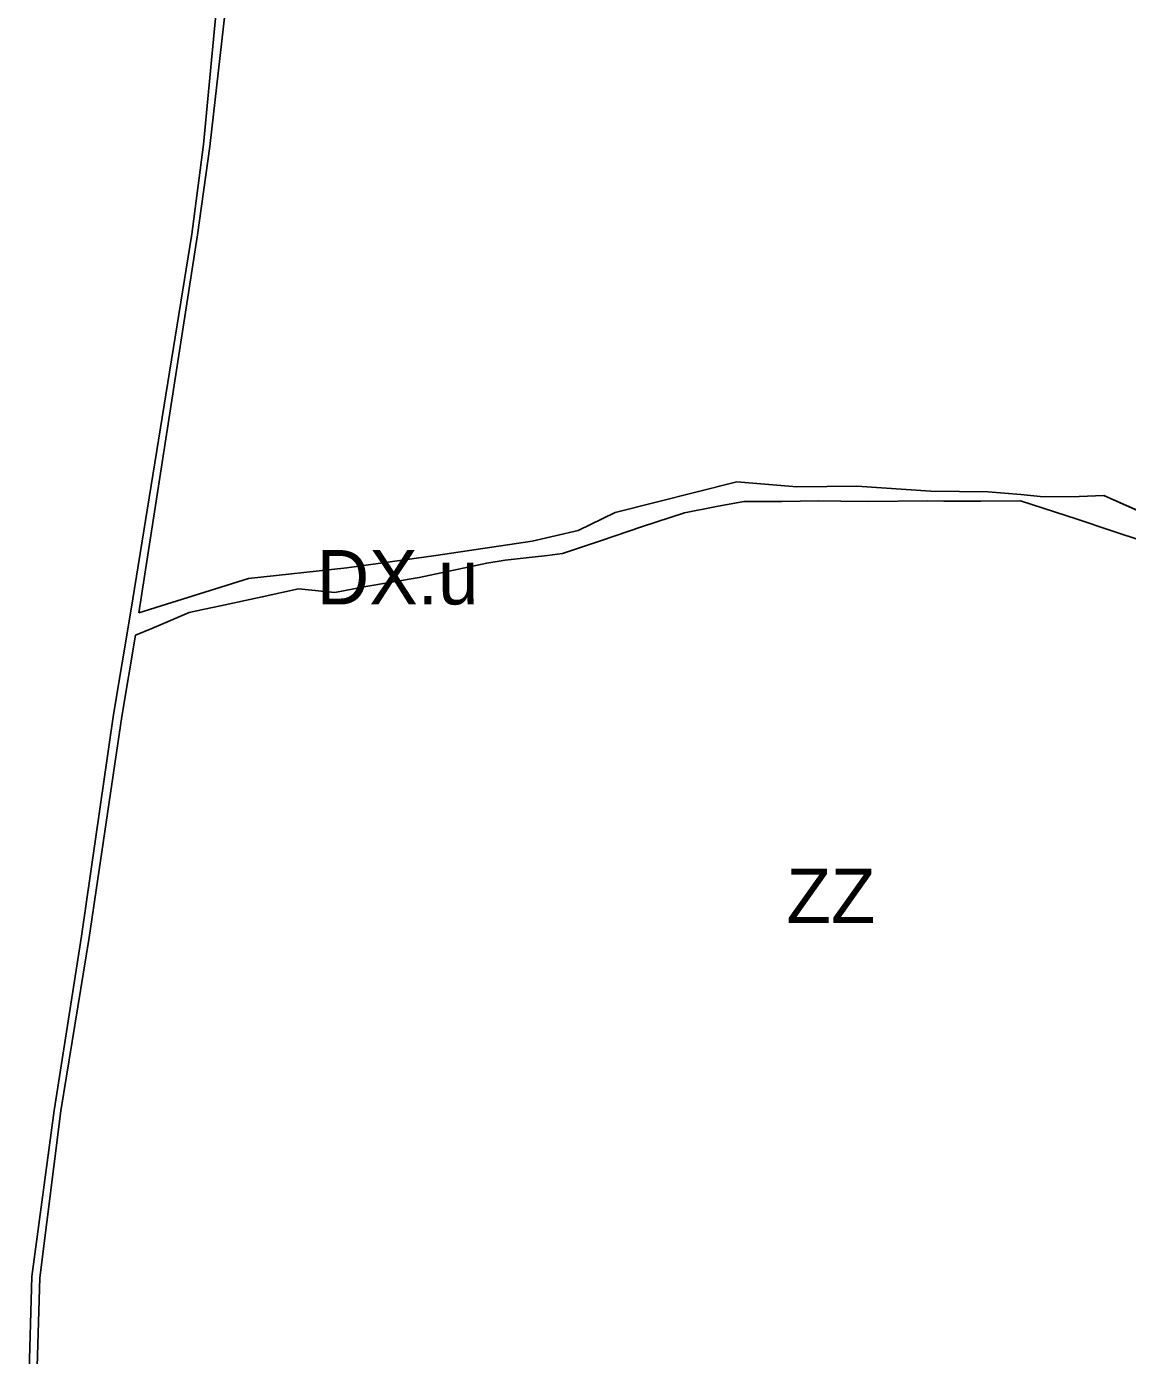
# Model space of a CAD drawing. Extents: x -555509 to -553005, y -1186756 to -1182560.
# Drawn here: x -555024.3 to -554741.3, y -1184380.7 to -1184039.1 of the extents above; entities that cross this region are included whole.
import ezdxf

# ---------------------------------------------------------------- set-up
doc = ezdxf.new("R2010")
doc.units = 0
for name, color, linetype in [('Level 26', 7, 'Continuous'), ('Level 59', 7, 'Continuous'), ('OBRYS_PLOCH', 7, 'Continuous'), ('stav_AP', 7, 'Continuous'), ('stav_ZZ', 7, 'Continuous')]:
    doc.layers.add(name, color=color, linetype=linetype)

msp = doc.modelspace()

# ---------------------------------------------------------------- linework, layer by layer
at = {"layer": 'Level 26'}
for p, q in [((-554977.25, -1184069.89), (-554972.59, -1184028.87)), ((-554981.81, -1184092.43), (-554997.53, -1184189.35)), ((-554841.71, -1184156.17), (-554872.97, -1184163.98)), ((-554777.04, -1184158.7), (-554791.86, -1184158.49)), ((-554753.68, -1184159.87), (-554762.83, -1184159.96)), ((-554747.36, -1184159.66), (-554753.68, -1184159.87)), ((-554872.97, -1184163.98), (-554882.51, -1184168.67)), ((-554882.51, -1184168.67), (-554894.36, -1184171.35)), ((-554967.28, -1184180.99), (-554995.48, -1184189.77)), ((-554997.53, -1184189.35), (-555002.02, -1184215.93)), ((-555002.02, -1184215.93), (-555010.19, -1184272.95)), ((-555010.19, -1184272.95), (-555017.27, -1184317.79)), ((-555017.27, -1184317.79), (-555022.95, -1184360.44))]:
    msp.add_line(p, q, dxfattribs=at)
for points in [[(-554971.89, -1183991.64), (-554974.97, -1184028.67), (-554978.81, -1184069.43), (-554981.81, -1184092.43)], [(-554995.48, -1184189.77), (-554980.39, -1184092.67), (-554977.25, -1184069.89)], [(-554791.86, -1184158.49), (-554810.85, -1184157.24), (-554826.25, -1184157.38), (-554841.71, -1184156.17)], [(-554996.33, -1184195.56), (-554992.16, -1184193.84), (-554982.55, -1184189.76), (-554978.55, -1184188.87), (-554974.47, -1184188.03), (-554963.73, -1184185.72), (-554954.41, -1184183.68), (-554945.1, -1184184.59), (-554937.1, -1184183.07), (-554923.4, -1184180.72), (-554906.02, -1184177.04), (-554901.25, -1184176.31), (-554894.31, -1184175.49), (-554890.43, -1184175.04), (-554886.56, -1184174.59), (-554876.77, -1184171.31), (-554865.93, -1184167.64), (-554855.16, -1184164.07), (-554846.93, -1184162.47), (-554839.91, -1184161.21)], [(-554839.91, -1184161.21), (-554835.01, -1184161.18), (-554830.1, -1184161.15), (-554820.74, -1184160.99), (-554814.94, -1184161.08), (-554807.82, -1184161.17), (-554792.65, -1184161.03), (-554788.5, -1184161.08), (-554779, -1184161.13), (-554768.81, -1184161.01), (-554754.23, -1184165.76)], [(-554762.83, -1184159.96), (-554768.67, -1184159.38), (-554777.04, -1184158.7)], [(-554718.94, -1184169.35), (-554731.96, -1184166.49), (-554747.36, -1184159.66)], [(-554754.23, -1184165.76), (-554745.55, -1184168.61), (-554737, -1184171.44), (-554731.66, -1184173.2), (-554726.32, -1184174.96), (-554718.61, -1184177.43), (-554714.69, -1184178.74), (-554710.61, -1184179.75)], [(-554894.36, -1184171.35), (-554919.07, -1184175.03), (-554942.01, -1184178.26), (-554967.28, -1184180.99)], [(-555019.26, -1184465.9), (-555022.34, -1184409.18), (-555020.93, -1184360.76), (-555015.55, -1184317.88), (-555008.27, -1184273.24), (-554999.82, -1184216.47), (-554996.33, -1184195.56)], [(-555022.95, -1184360.44), (-555024.33, -1184409.14), (-555021.51, -1184466.21)]]:
    msp.add_lwpolyline(points, dxfattribs=at)
at = {"layer": 'OBRYS_PLOCH'}
for p, q in [((-554977.25, -1184069.89), (-554972.59, -1184028.87)), ((-554972.59, -1184028.87), (-554977.25, -1184069.89)), ((-554981.81, -1184092.43), (-554997.53, -1184189.35)), ((-554841.71, -1184156.17), (-554872.97, -1184163.98)), ((-554872.97, -1184163.98), (-554841.71, -1184156.17)), ((-554841.71, -1184156.17), (-554826.25, -1184157.38)), ((-554826.25, -1184157.38), (-554810.85, -1184157.24)), ((-554810.85, -1184157.24), (-554791.86, -1184158.49)), ((-554839.91, -1184161.21), (-554846.93, -1184162.47)), ((-554835.01, -1184161.18), (-554839.91, -1184161.21)), ((-554830.1, -1184161.15), (-554835.01, -1184161.18)), ((-554820.74, -1184160.99), (-554830.1, -1184161.15)), ((-554814.94, -1184161.08), (-554820.74, -1184160.99)), ((-554807.82, -1184161.17), (-554814.94, -1184161.08)), ((-554792.65, -1184161.03), (-554807.82, -1184161.17)), ((-554788.5, -1184161.08), (-554792.65, -1184161.03)), ((-554777.04, -1184158.7), (-554791.86, -1184158.49)), ((-554791.86, -1184158.49), (-554777.04, -1184158.7)), ((-554779, -1184161.13), (-554788.5, -1184161.08)), ((-554777.04, -1184158.7), (-554768.67, -1184159.38)), ((-554753.68, -1184159.87), (-554762.83, -1184159.96)), ((-554747.36, -1184159.66), (-554753.68, -1184159.87)), ((-554753.68, -1184159.87), (-554747.36, -1184159.66)), ((-554747.36, -1184159.66), (-554731.96, -1184166.49)), ((-554872.97, -1184163.98), (-554882.51, -1184168.67)), ((-554882.51, -1184168.67), (-554872.97, -1184163.98)), ((-554865.93, -1184167.64), (-554876.77, -1184171.31)), ((-554882.51, -1184168.67), (-554894.36, -1184171.35)), ((-554894.36, -1184171.35), (-554882.51, -1184168.67)), ((-554876.77, -1184171.31), (-554886.56, -1184174.59)), ((-554886.56, -1184174.59), (-554890.43, -1184175.04)), ((-554967.28, -1184180.99), (-554942.01, -1184178.26)), ((-554901.25, -1184176.31), (-554906.02, -1184177.04)), ((-554967.28, -1184180.99), (-554995.48, -1184189.77)), ((-554995.48, -1184189.77), (-554967.28, -1184180.99)), ((-554954.41, -1184183.68), (-554963.73, -1184185.72)), ((-554945.1, -1184184.59), (-554954.41, -1184183.68)), ((-554937.1, -1184183.07), (-554945.1, -1184184.59)), ((-554974.47, -1184188.03), (-554978.55, -1184188.87)), ((-554963.73, -1184185.72), (-554974.47, -1184188.03)), ((-554997.53, -1184189.35), (-555002.02, -1184215.93)), ((-554982.55, -1184189.76), (-554992.16, -1184193.84)), ((-554978.55, -1184188.87), (-554982.55, -1184189.76)), ((-554992.16, -1184193.84), (-554996.33, -1184195.56)), ((-554996.33, -1184195.56), (-554999.82, -1184216.47)), ((-555002.02, -1184215.93), (-555010.19, -1184272.95)), ((-554999.82, -1184216.47), (-555008.27, -1184273.24)), ((-555010.19, -1184272.95), (-555017.27, -1184317.79)), ((-555008.27, -1184273.24), (-555015.55, -1184317.88)), ((-555017.27, -1184317.79), (-555022.95, -1184360.44))]:
    msp.add_line(p, q, dxfattribs=at)
for points in [[(-554971.89, -1183991.64), (-554974.97, -1184028.67), (-554978.81, -1184069.43), (-554981.81, -1184092.43)], [(-554995.48, -1184189.77), (-554980.39, -1184092.67), (-554977.25, -1184069.89)], [(-554977.25, -1184069.89), (-554980.39, -1184092.67), (-554995.48, -1184189.77)], [(-554791.86, -1184158.49), (-554810.85, -1184157.24), (-554826.25, -1184157.38), (-554841.71, -1184156.17)], [(-554996.33, -1184195.56), (-554992.16, -1184193.84), (-554982.55, -1184189.76), (-554978.55, -1184188.87), (-554974.47, -1184188.03), (-554963.73, -1184185.72), (-554954.41, -1184183.68), (-554945.1, -1184184.59), (-554937.1, -1184183.07), (-554923.4, -1184180.72), (-554906.02, -1184177.04), (-554901.25, -1184176.31), (-554894.31, -1184175.49), (-554890.43, -1184175.04), (-554886.56, -1184174.59), (-554876.77, -1184171.31), (-554865.93, -1184167.64), (-554855.16, -1184164.07), (-554846.93, -1184162.47), (-554839.91, -1184161.21)], [(-554839.91, -1184161.21), (-554835.01, -1184161.18), (-554830.1, -1184161.15), (-554820.74, -1184160.99), (-554814.94, -1184161.08), (-554807.82, -1184161.17), (-554792.65, -1184161.03), (-554788.5, -1184161.08), (-554779, -1184161.13), (-554768.81, -1184161.01), (-554754.23, -1184165.76)], [(-554754.23, -1184165.76), (-554768.81, -1184161.01), (-554779, -1184161.13)], [(-554762.83, -1184159.96), (-554768.67, -1184159.38), (-554777.04, -1184158.7)], [(-554768.67, -1184159.38), (-554762.83, -1184159.96), (-554753.68, -1184159.87)], [(-554718.94, -1184169.35), (-554731.96, -1184166.49), (-554747.36, -1184159.66)], [(-554846.93, -1184162.47), (-554855.16, -1184164.07), (-554865.93, -1184167.64)], [(-554754.23, -1184165.76), (-554745.55, -1184168.61), (-554737, -1184171.44), (-554731.66, -1184173.2), (-554726.32, -1184174.96), (-554718.61, -1184177.43), (-554714.69, -1184178.74), (-554710.61, -1184179.75)], [(-554731.66, -1184173.2), (-554737, -1184171.44), (-554745.55, -1184168.61), (-554754.23, -1184165.76)], [(-554894.36, -1184171.35), (-554919.07, -1184175.03), (-554942.01, -1184178.26), (-554967.28, -1184180.99)], [(-554942.01, -1184178.26), (-554919.07, -1184175.03), (-554894.36, -1184171.35)], [(-554906.02, -1184177.04), (-554923.4, -1184180.72), (-554937.1, -1184183.07)], [(-554890.43, -1184175.04), (-554894.31, -1184175.49), (-554901.25, -1184176.31)], [(-555019.26, -1184465.9), (-555022.34, -1184409.18), (-555020.93, -1184360.76), (-555015.55, -1184317.88), (-555008.27, -1184273.24), (-554999.82, -1184216.47), (-554996.33, -1184195.56)], [(-555015.55, -1184317.88), (-555020.93, -1184360.76), (-555022.34, -1184409.18)], [(-555022.95, -1184360.44), (-555024.33, -1184409.14), (-555021.51, -1184466.21)]]:
    msp.add_lwpolyline(points, dxfattribs=at)
at = {"layer": 'stav_AP'}
for p, q in [((-554972.59, -1184028.87), (-554977.25, -1184069.89)), ((-554995.48, -1184189.77), (-554967.28, -1184180.99))]:
    msp.add_line(p, q, dxfattribs=at)
for points in [[(-554841.71, -1184156.17), (-554826.25, -1184157.38), (-554810.85, -1184157.24), (-554791.86, -1184158.49), (-554777.04, -1184158.7), (-554768.67, -1184159.38), (-554762.83, -1184159.96), (-554753.68, -1184159.87), (-554747.36, -1184159.66), (-554731.96, -1184166.49), (-554718.94, -1184169.35), (-554690.31, -1184175.13), (-554686.37, -1184112.37), (-554680.44, -1184061.29), (-554676.39, -1184008.4)], [(-554977.25, -1184069.89), (-554980.39, -1184092.67), (-554995.48, -1184189.77)], [(-554967.28, -1184180.99), (-554942.01, -1184178.26), (-554919.07, -1184175.03), (-554894.36, -1184171.35), (-554882.51, -1184168.67), (-554872.97, -1184163.98), (-554841.71, -1184156.17)]]:
    msp.add_lwpolyline(points, dxfattribs=at)
at = {"layer": 'stav_ZZ'}
for p, q in [((-554835.01, -1184161.18), (-554839.91, -1184161.21)), ((-554830.1, -1184161.15), (-554835.01, -1184161.18)), ((-554820.74, -1184160.99), (-554830.1, -1184161.15)), ((-554814.94, -1184161.08), (-554820.74, -1184160.99)), ((-554779, -1184161.13), (-554788.5, -1184161.08)), ((-554768.81, -1184161.01), (-554779, -1184161.13)), ((-554754.23, -1184165.76), (-554768.81, -1184161.01)), ((-554855.16, -1184164.07), (-554865.93, -1184167.64)), ((-554865.93, -1184167.64), (-554876.77, -1184171.31)), ((-554745.55, -1184168.61), (-554754.23, -1184165.76)), ((-554737, -1184171.44), (-554745.55, -1184168.61)), ((-554954.41, -1184183.68), (-554963.73, -1184185.72)), ((-554945.1, -1184184.59), (-554954.41, -1184183.68)), ((-554978.55, -1184188.87), (-554982.55, -1184189.76)), ((-554996.33, -1184195.56), (-554999.82, -1184216.47))]:
    msp.add_line(p, q, dxfattribs=at)
for points in [[(-554839.91, -1184161.21), (-554846.93, -1184162.47), (-554855.16, -1184164.07)], [(-554788.5, -1184161.08), (-554792.65, -1184161.03), (-554807.82, -1184161.17), (-554814.94, -1184161.08)], [(-554876.77, -1184171.31), (-554886.56, -1184174.59), (-554890.43, -1184175.04), (-554894.31, -1184175.49), (-554901.25, -1184176.31)], [(-554901.25, -1184176.31), (-554906.02, -1184177.04), (-554923.4, -1184180.72), (-554937.1, -1184183.07), (-554945.1, -1184184.59)], [(-554963.73, -1184185.72), (-554974.47, -1184188.03), (-554978.55, -1184188.87)], [(-554982.55, -1184189.76), (-554992.16, -1184193.84), (-554996.33, -1184195.56)], [(-554999.82, -1184216.47), (-555008.27, -1184273.24), (-555015.55, -1184317.88)], [(-555015.55, -1184317.88), (-555020.93, -1184360.76), (-555022.34, -1184409.18)]]:
    msp.add_lwpolyline(points, dxfattribs=at)

# ---------------------------------------------------------------- texts
at = {"layer": 'Level 59'}
for s, p in [('DX.u', (-554949.74, -1184187.65)), ('ZZ', (-554828.95, -1184269.59))]:
    msp.add_text(s, height=14, dxfattribs=at).set_placement(p)

doc.saveas('drawing.dxf')
